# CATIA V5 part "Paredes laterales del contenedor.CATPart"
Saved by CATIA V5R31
Part number: Paredes laterales del contenedor
Bounding box of the stored display mesh (mm): x -70 to 70, y -3.3 to 300, z 0 to 3.3
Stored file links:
  C:\Users\189361\Desktop\Paredes laterales del contenedor.CATPart
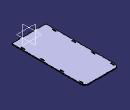
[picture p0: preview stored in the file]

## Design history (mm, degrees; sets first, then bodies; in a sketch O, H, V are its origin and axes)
Set1 "sketch"
  Sketch1 on xy-plane, origin (0, 0, 0), H (1, 0, 0), V (0, 1, 0)
    line L1 (0, 0) -> (-22.1, 0)
    point P1 (-22.1, 0)
    line L2 (-22.1, 0) -> (-22.1, -3.3)
    point P2 (-22.1, -3.3)
    line L3 (-22.1, -3.3) -> (-37.9, -3.3)
    point P3 (-37.9, -3.3)
    line L4 (-37.9, -3.3) -> (-37.9, 0)
    point P4 (-37.9, 0)
    line L5 (-37.9, 0) -> (-70, 0)
    point P5 (-70, 0)
    line L6 (-70, 0) -> (-70, 285)
    point P6 (-70, 300)
    line L7 (-55, 300) -> (0, 300)
    point P7 (0, 300)
    construction line L8 (-30, -20.1147) -> (-30, 19.0765)
    point P8 (-30, -20.1147)
    point P9 (-30, 19.0765)
    arc A1 centre (-55, 285) radius 15 from (-70, 285) to (-55, 300) cw
    point P10 (-70, 285)
    point P11 (-55, 300)
    point P13 (-66, 32.5)
    line L9 (-66, 32.5) -> (-62.7, 32.5)
    line L10 (-62.7, 32.5) -> (-62.7, 47.5)
    line L11 (-62.7, 47.5) -> (-66, 47.5)
    line L12 (-66, 47.5) -> (-66, 32.5)
    point P14 (-62.7, 32.5)
    point P15 (-62.7, 47.5)
    point P16 (-66, 47.5)
    construction line L13 (-95.2529, 40) -> (-58.138, 40)
    point P17 (-95.2529, 40)
    point P18 (-58.138, 40)
    construction line L14 (-91.6192, 80) -> (-26.4736, 80)
    point P19 (-91.6192, 80)
    point P20 (-26.4736, 80)
    point P21 (-66, 127.5)
    point P22 (-62.7, 127.5)
    point P23 (-62.7, 112.5)
    point P24 (-66, 112.5)
    line L15 (-66, 127.5) -> (-62.7, 127.5)
    line L16 (-62.7, 127.5) -> (-62.7, 112.5)
    line L17 (-62.7, 112.5) -> (-66, 112.5)
    line L18 (-66, 112.5) -> (-66, 127.5)
    axis line L19 (-9.0841, 160) -> (-80.1993, 160)
    point P26 (-80.1993, 160)
    point P27 (-58.138, 120)
    point P28 (-95.2529, 120)
    construction line L20 (-95.2529, 120) -> (-58.138, 120)
    point P29 (-66, 287.5)
    point P30 (-62.7, 287.5)
    point P31 (-62.7, 272.5)
    point P32 (-66, 272.5)
    point P33 (-66, 192.5)
    point P34 (-62.7, 192.5)
    point P35 (-62.7, 207.5)
    point P36 (-66, 207.5)
    line L21 (-66, 287.5) -> (-62.7, 287.5)
    line L22 (-62.7, 287.5) -> (-62.7, 272.5)
    line L23 (-62.7, 272.5) -> (-66, 272.5)
    line L24 (-66, 272.5) -> (-66, 287.5)
    line L25 (-66, 192.5) -> (-62.7, 192.5)
    line L26 (-62.7, 192.5) -> (-62.7, 207.5)
    line L27 (-62.7, 207.5) -> (-66, 207.5)
    line L28 (-66, 207.5) -> (-66, 192.5)
    point P37 (22.1, 0)
    point P38 (22.1, -3.3)
    point P39 (37.9, -3.3)
    point P40 (37.9, 0)
    point P41 (70, 0)
    point P42 (70, 300)
    point P43 (30, 19.0765)
    point P44 (30, -20.1147)
    construction line L29 (30, -20.1147) -> (30, 19.0765)
    point P45 (70, 285)
    point P46 (55, 300)
    point P48 (66, 32.5)
    point P49 (62.7, 32.5)
    point P50 (62.7, 47.5)
    point P51 (66, 47.5)
    point P52 (58.138, 40)
    point P53 (26.4736, 80)
    point P54 (91.6192, 80)
    construction line L30 (91.6192, 80) -> (26.4736, 80)
    point P55 (66, 127.5)
    point P56 (62.7, 127.5)
    point P57 (62.7, 112.5)
    point P58 (66, 112.5)
    point P59 (80.1993, 160)
    point P60 (58.138, 120)
    point P61 (66, 287.5)
    point P62 (62.7, 287.5)
    point P63 (62.7, 272.5)
    point P64 (66, 272.5)
    point P65 (66, 192.5)
    point P66 (62.7, 192.5)
    point P67 (62.7, 207.5)
    point P68 (66, 207.5)
    line L31 (22.1, 0) -> (22.1, -3.3)
    line L32 (22.1, -3.3) -> (37.9, -3.3)
    line L33 (37.9, -3.3) -> (37.9, 0)
    line L34 (37.9, 0) -> (70, 0)
    line L35 (70, 0) -> (70, 285)
    arc A2 centre (55, 285) radius 15 from (70, 285) to (55, 300) ccw
    line L36 (66, 32.5) -> (62.7, 32.5)
    line L37 (62.7, 32.5) -> (62.7, 47.5)
    line L38 (62.7, 47.5) -> (66, 47.5)
    line L39 (66, 47.5) -> (66, 32.5)
    line L40 (66, 127.5) -> (62.7, 127.5)
    line L41 (62.7, 127.5) -> (62.7, 112.5)
    line L42 (62.7, 112.5) -> (66, 112.5)
    line L43 (66, 112.5) -> (66, 127.5)
    line L44 (66, 287.5) -> (62.7, 287.5)
    line L45 (62.7, 287.5) -> (62.7, 272.5)
    line L46 (62.7, 272.5) -> (66, 272.5)
    line L47 (66, 272.5) -> (66, 287.5)
    line L48 (66, 192.5) -> (62.7, 192.5)
    line L49 (62.7, 192.5) -> (62.7, 207.5)
    line L50 (62.7, 207.5) -> (66, 207.5)
    line L51 (66, 207.5) -> (66, 192.5)
    point P69 (0, 0)
    line L52 (0, 0) -> (22.1, 0)
    point P70 (0, 300)
    line L53 (55, 300) -> (0, 300)
    distance V L8 = 30
    distance L2 L8 = 7.9
    distance L8 L4 = 7.9
    length L4 = 3.3
    distance V L6 = 70
    distance P5 P6 = 300
    radius A1 = 15
    length L12 = 15
    length L11 = 3.3
    distance L13 L11 = 7.5
    distance L5 L13 = 40
    distance L13 L14 = 40
    distance L20 L19 = 40
    distance L12 L6 = 4
    horizontal: L1 H, L3 H, L5 H, L7 H, L9 H, L11 H, L13 H, L14 H, L19 H
    vertical: L2 V, L4 V, L6 V, L8 V, L10 V, L12 V
    coincidence: P4 H, P7 V, L6 P6, L7 P6, O P69, P7 P70
    tangency: A1 L6, A1 L7
    symmetry: P13 P21 L14, P14 P22 L14, P15 P23 L14, P16 P24 L14, L9 L15 L14, L10 L16 L14, L11 L17 L14, L12 L18 L14, P18 P27 L14, P17 P28 L14, L13 L20 L14, P13 P29 L19, P14 P30 L19, P15 P31 L19, P16 P32 L19, P21 P33 L19, P22 P34 L19, P23 P35 L19, P24 P36 L19, L9 L21 L19, L10 L22 L19, L11 L23 L19, L12 L24 L19, L15 L25 L19, L16 L26 L19, L17 L27 L19, L18 L28 L19, P1 P37 V, P2 P38 V, P3 P39 V, P4 P40 V, P5 P41 V, P6 P42 V, P9 P43 V, P8 P44 V, L8 L29 V, P10 P45 V, P11 P46 V, P13 P48 V, P14 P49 V, P15 P50 V, P16 P51 V, P18 P52 V, P20 P53 V, P19 P54 V, L14 L30 V, P21 P55 V, P22 P56 V, P23 P57 V, P24 P58 V, P26 P59 V, P27 P60 V, P29 P61 V, P30 P62 V, P31 P63 V, P32 P64 V, P33 P65 V, P34 P66 V, P35 P67 V, P36 P68 V, L2 L31 V, L3 L32 V, L4 L33 V, L5 L34 V, L6 L35 V, A1 A2 V, L9 L36 V, L10 L37 V, L11 L38 V, L12 L39 V, L15 L40 V, L16 L41 V, L17 L42 V, L18 L43 V, L21 L44 V, L22 L45 V, L23 L46 V, L24 L47 V, L25 L48 V, L26 L49 V, L27 L50 V, L28 L51 V, O P69 V, L1 L52 V, P7 P70 V, L7 L53 V
Body1 (main body)
  Pad1: profile Sketch1, direction (0, 0, 1), length 3.3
